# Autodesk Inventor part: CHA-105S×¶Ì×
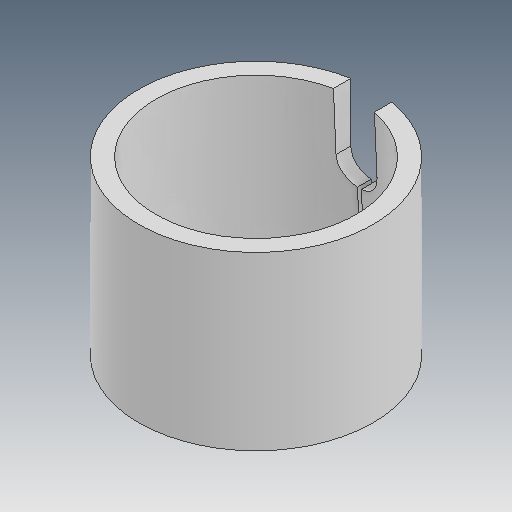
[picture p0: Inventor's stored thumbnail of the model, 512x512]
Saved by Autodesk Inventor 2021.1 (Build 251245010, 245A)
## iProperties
Created: 2019-05
Part Number: CHA-105S×¶Ì×
Material: Ogólny
Document SubType Name: Modeling
Designer: user
Density: 1 g/cm^3
Appearance: Domyślna
Author: user
Revision Number: ÈÎºÎ
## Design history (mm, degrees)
feature "ÊäÈë1"
node "Bryła1"
